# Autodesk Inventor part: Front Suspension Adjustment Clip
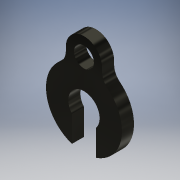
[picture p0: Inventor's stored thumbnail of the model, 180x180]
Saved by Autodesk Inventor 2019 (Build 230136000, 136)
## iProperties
Shininess: 41.0
Compacted: True
Length Units: 11272
Angle Units: 11279
Time Units: 11290
Mass Units: 11286
Length Display Precision: 3
Angle Display Precision: 2
Company: Autodesk
Created: 2001-02
Part Number: Front Suspension Adjustment Clip
Document SubType Name: Modeling
Designer: Autodesk, Inc.
Project: Inventor Samples
Density: 1.13 g/cm^3
Material: Nylon-6/6
Mass: 0.0594254 g
Surface Area: 1.41637 cm^2
Volume: 0.0525888 cm^3
Appearance: Gunmetal
Density: 0.0
Volumn: 0.0
Area: 0.0
PropertySet Name: Model Information
Control State: 0
Master: False
Checked Out: False
Checked Out Date: 2018-05-30
Last Check In Date: 2018-05-30
Author: Autodesk, Inc.
Revision Number: A
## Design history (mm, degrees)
sketch "Sketch1"
  geometry: L1 (1.937, 15.448)-(1.937, 16.693); L2 (5.747, 16.693)-(5.747, 15.448); L3 (2.572, 10.876)-(2.572, 8.137); L4 (5.112, 10.876)-(5.112, 8.137); C1 r 1.048 at (3.842, 16.693); A1 r 1.651 centre (3.842, 11.931) between (5.112, 10.876) and (2.572, 10.876); A2 r 1.905 centre (3.842, 16.693) between (5.747, 16.693) and (1.937, 16.693); A3 r 4.001 centre (3.842, 11.931) between (1.937, 15.448) and (2.572, 8.137); A4 r 4.001 centre (3.842, 11.931) between (5.112, 8.137) and (5.747, 15.448)
  constraints: 8 end point, 8 point on circle, 5 centre point, 4 parallel, 2 coincident, 2 tangent, 1 concentric, 1 vertical, 1 other
  dimensions: "d1" = 3.302 diameter of A1; "d2" = 1.905 radius of A2; "d3" = 2.0955 diameter of C1; "d4" = 4.7625 distance of A3.centre A2.centre; "d5" = 2.54 distance between parallel lines of L4 L3; "d6" = 1.27 distance from line of A3.centre L3 (= 0.5 x d5); "d7" = 4.0005 radius of A4
extrude "Extrusion1" new body sketch "Sketch1" distance "d8" = 1.27; taper "d9" = 0 deg
fillet "Fillet1" dims "d10" = 1.5875
body "Solid1"
other parameters: "d0" = 4.0005
